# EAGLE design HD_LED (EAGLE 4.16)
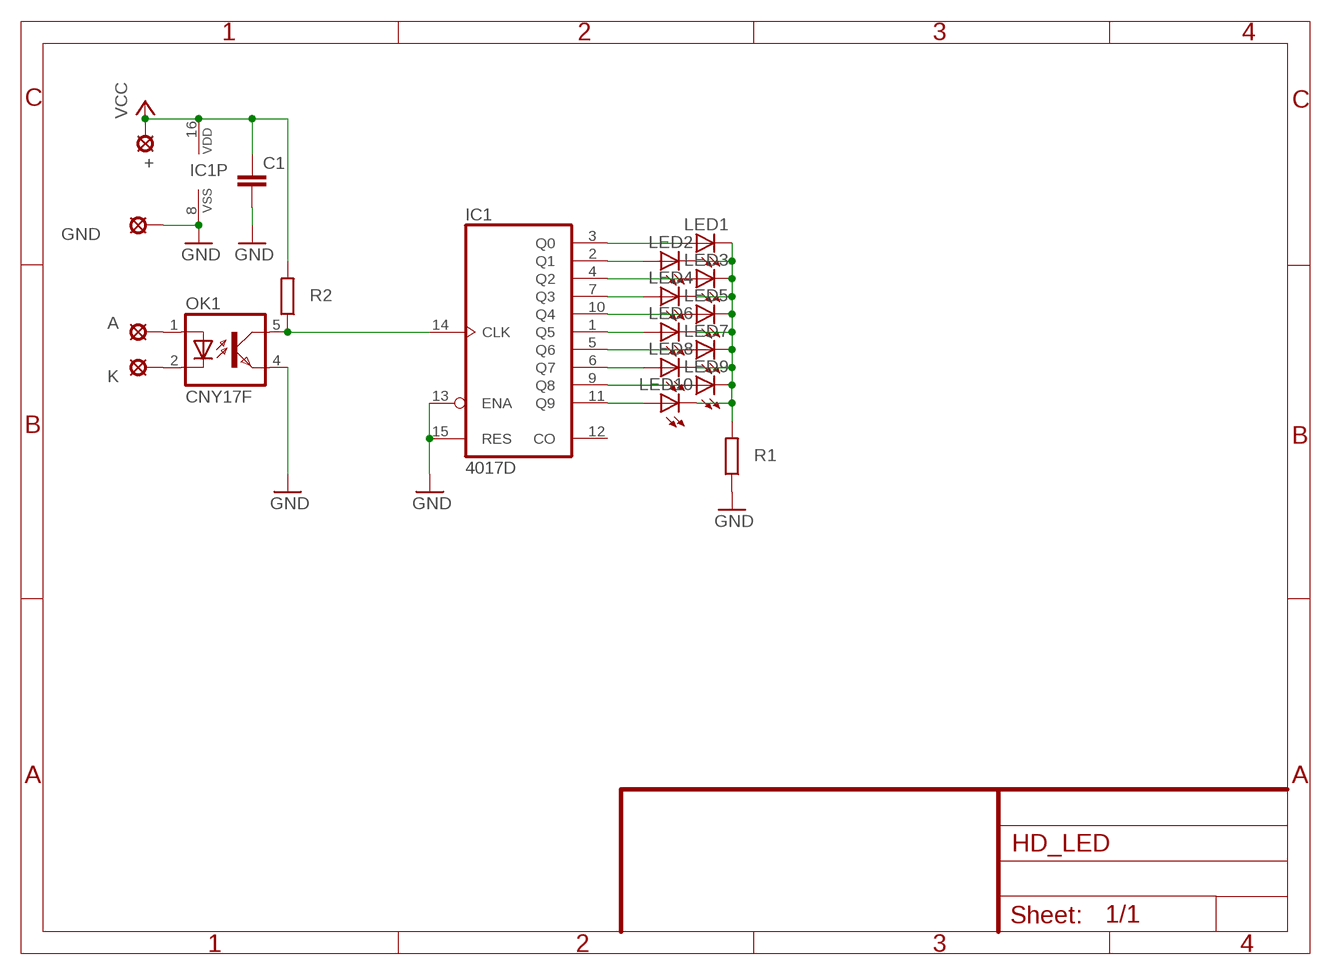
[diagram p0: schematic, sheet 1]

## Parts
+  LSP10  [LSP10]
A  LSP10  [LSP10]
C1  C-EUC0805  [C0805]
GND  LSP10  [LSP10]
IC1  4017D  [SO16]
K  LSP10  [LSP10]
LED1  LED3MM  [LED3MM]
LED2  LED3MM  [LED3MM]
LED3  LED3MM  [LED3MM]
LED4  LED3MM  [LED3MM]
LED5  LED3MM  [LED3MM]
LED6  LED3MM  [LED3MM]
LED7  LED3MM  [LED3MM]
LED8  LED3MM  [LED3MM]
LED9  LED3MM  [LED3MM]
LED10  LED3MM  [LED3MM]
OK1  CNY17F  [DIL06]
R1  R-EU_R0805  [R0805]
R2  R-EU_R0805  [R0805]

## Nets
GND: C1.2 GND.MP IC1.8(VSS) IC1.13(ENA) IC1.15(RES) OK1.4(EMIT) R1.1
N$1: IC1.3(Q0) LED1.A
N$2: IC1.2(Q1) LED2.A
N$3: IC1.4(Q2) LED3.A
N$4: IC1.7(Q3) LED4.A
N$5: IC1.10(Q4) LED5.A
N$6: IC1.1(Q5) LED6.A
N$7: IC1.5(Q6) LED7.A
N$8: IC1.6(Q7) LED8.A
N$9: IC1.9(Q8) LED9.A
N$10: IC1.11(Q9) LED10.A
N$11: LED1.K(C) LED2.K(C) LED3.K(C) LED4.K(C) LED5.K(C) LED6.K(C) LED7.K(C) LED8.K(C) LED9.K(C) LED10.K(C) R1.2
N$12: A.MP OK1.1(A)
N$13: IC1.14(CLK) OK1.5(COL) R2.1
N$14: K.MP OK1.2(C)
VCC: +.MP C1.1 IC1.16(VDD) R2.2
Unconnected: IC1.12(CO)

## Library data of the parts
+ A GND K = solpad:LSP10: SOLDER PAD
C1 = rcl:C-EU: CAPACITOR, European symbol
IC1 = 40xx:4017: COUNTER/DIVIDER
LED1-LED10 = led:LED: LED
OK1 = optocoupler:CNY17F: SIEMENS OPTO COUPLER
R1 R2 = rcl:R-EU_: RESISTOR, European symbol

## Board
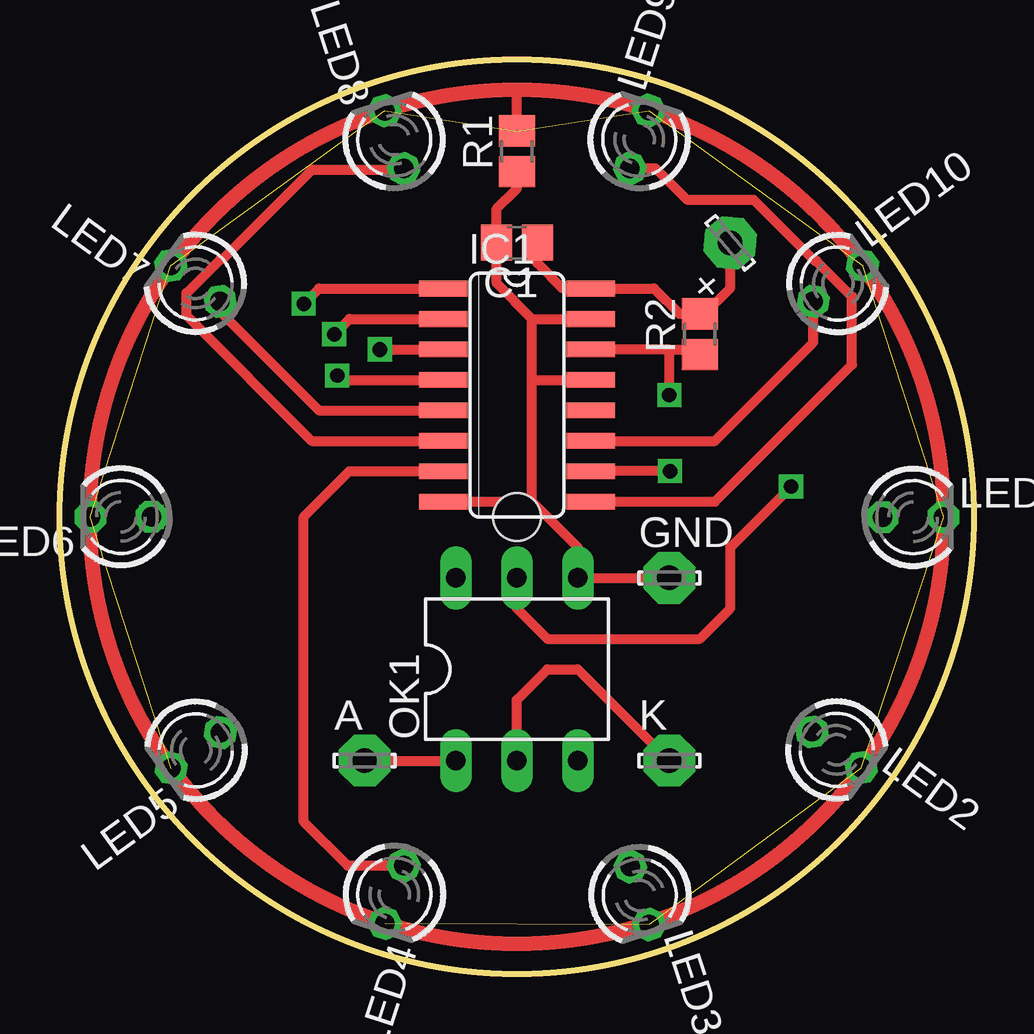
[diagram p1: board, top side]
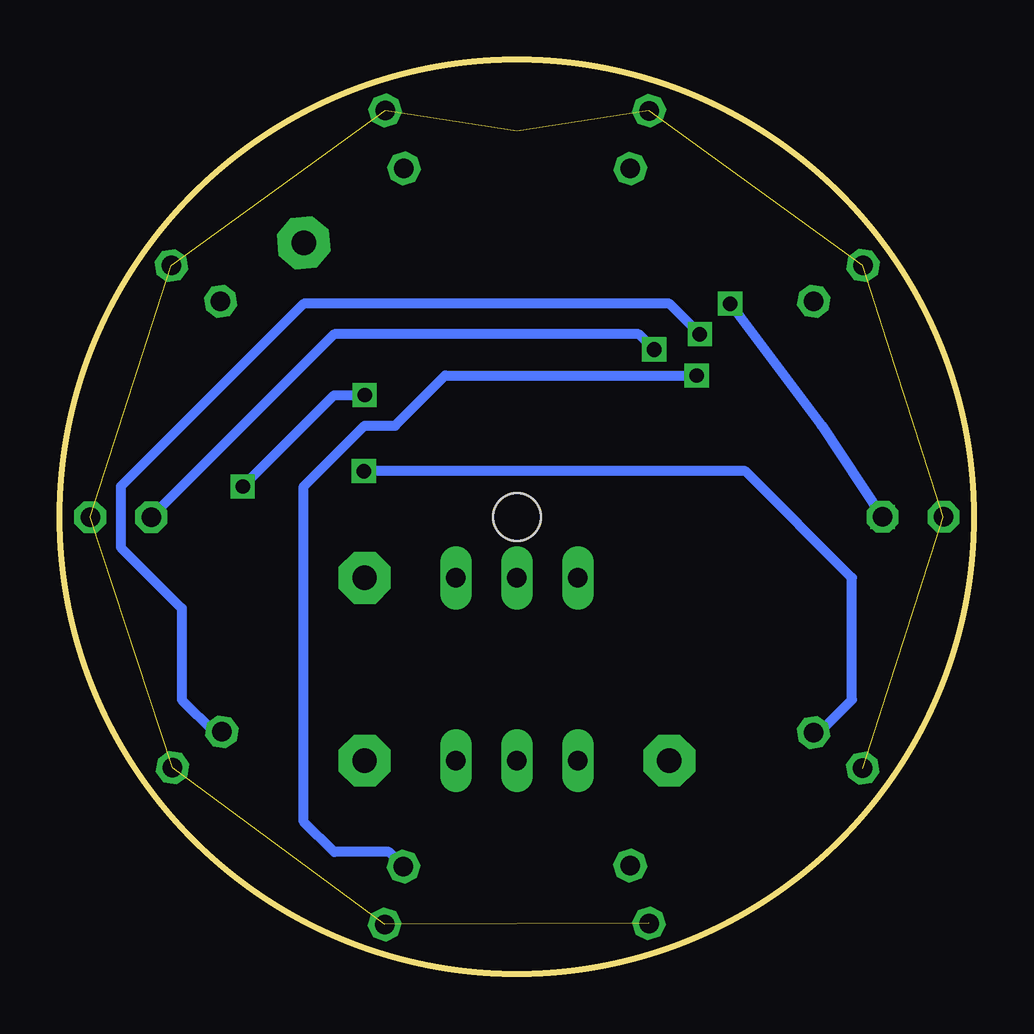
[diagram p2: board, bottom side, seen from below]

Size 38.1 x 38.1 mm. Coordinates in mm from the lower left corner, seen from the top.
Outline: circle at 19.05,19.05 radius 19.05
Copper layers (1*16): Top 0.035mm / dielectric 1.5mm / Bottom 0.035mm
Design rules "default": minimum track width 10mil, minimum drill 24mil, track to track 8mil, track to pad 8mil, pad to pad 8mil, via to via 8mil, smd to smd 8mil, copper to edge 40mil, drill to drill 8mil, minimum pad ring 10mil, minimum via ring 8mil, stop-mask expansion 4mil, vias tented up to drill 0mil, thermal gap 10mil
Holes 2 mm at 19.05,19.05

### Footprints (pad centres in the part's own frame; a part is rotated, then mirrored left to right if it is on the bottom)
LSP10 = drill 1.016 pad 2.159 octagon: MP 0,0
C0805 = smd 1.3 x 1.5: 1 -0.85,0; 2 0.85,0
SO16 = smd 0.66 x 2.032: 1 -4.445,-3.073; 2 -3.175,-3.073; 3 -1.905,-3.073; 4 -0.635,-3.073; 5 0.635,-3.073; 6 1.905,-3.073; 7 3.175,-3.073; 8 4.445,-3.073; 9 4.445,3.073; 10 3.175,3.073; 11 1.905,3.073; 12 0.635,3.073; 13 -0.635,3.073; 14 -1.905,3.073; 15 -3.175,3.073; 16 -4.445,3.073
LED3MM = drill 0.813 octagon: A -1.27,0; K 1.27,0
DIL06 = drill 0.813 long: 1 -2.54,-3.81; 2 0,-3.81; 3 2.54,-3.81; 4 2.54,3.81; 5 0,3.81; 6 -2.54,3.81
R0805 = smd 1.3 x 1.5: 1 -0.85,0; 2 0.85,0

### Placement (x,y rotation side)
+  27.94,30.48 130 top
A  12.7,8.89 0 top
C1  19.05,30.48 180 top
GND  25.4,16.51 0 top
IC1  19.05,24.13 270 top
K  25.4,8.89 0 top
LED1  35.57,19.04 0 top
LED2  32.38,9.34 324 top
LED3  24.17,3.27 288 top
LED4  13.94,3.31 252 top
LED5  5.66,9.32 216 top
LED6  2.54,19.05 180 top
LED7  5.65,28.79 144 top
LED8  13.93,34.78 108 top
LED9  24.15,34.79 72 top
LED10  32.43,28.78 36 top
OK1  19.05,12.7 0 top
R1  19.05,34.29 90 top
R2  26.67,26.67 90 top

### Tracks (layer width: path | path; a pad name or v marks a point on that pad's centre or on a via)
GND
  Top 0.406: R1.1 19.05,32.73 18.6,32.28 18.6,32.3 | 18.6,32.3 | 18.6,32.3 18.2,31.89 C1.2 18.2,28.79 19.68,27.3 | 19.68,27.3 IC1.15 | 19.68,24.77 IC1.13 | 19.68,24.77 19.68,27.3 | IC1.8 19.68,19.68 | 19.68,19.68 19.68,24.77 | 19.68,19.68 21.59,17.78 OK1.4 GND.MP
N$1  (via drill 0.6)
  Top 0.406: IC1.3 v13.34,26.04 v13.33,26.02
  Bottom 0.406: LED1.A 26.67,26.67 13.97,26.67 v13.34,26.04
N$2  (via drill 0.6)
  Top 0.406: IC1.2 12.06,27.3 v11.43,26.67
  Bottom 0.406: v11.43,26.67 12.7,27.94 27.94,27.94 35.56,20.32 35.56,17.78 33.02,15.24 33.02,11.43 31.68,10.09 LED2.A
N$3  (via drill 0.6)
  Top 0.406: IC1.4 11.74,24.77 v11.56,24.94
  Bottom 0.406: v11.56,24.94 22.05,24.94 24.13,22.86 25.4,22.86 27.94,20.32 27.94,6.35 26.67,5.08 24.38,5.08 LED3.A
N$4
  Top 0.406: IC1.7 12.06,20.95 10.16,19.05 10.16,6.35 11.99,4.52 LED4.A
N$5  (via drill 0.6)
  Top 0.406: IC1.10 v25.42,20.95 v25.43,20.96
  Bottom 0.406: v25.43,20.96 9.53,20.96 5.08,16.51 5.08,11.43 6.44,10.07 LED5.A
N$6  (via drill 0.6)
  Top 0.406: IC1.1 10.79,28.57 v10.16,27.94 | LED6.A
  Bottom 0.406: v10.16,27.94 6.35,22.86 LED6.A
  other vias: 3.81,19.05
N$7
  Top 0.406: LED7.A 6.68,27.61 10.79,23.5 IC1.5
N$8
  Top 0.406: IC1.6 10.5,22.23 5.27,27.45 5.27,28.38 6.69,29.8 6.78,29.8 10.51,33.54 14.36,33.54 | 14.36,33.54 14.37,33.54 | 14.36,33.54 LED8.A
N$9
  Top 0.406: IC1.9 27.3,19.68 33.02,25.4 33.02,28.24 31.54,29.72 31.46,29.72 28.93,32.26 26.16,32.26 24.84,33.58 LED9.A
N$10
  Top 0.406: IC1.11 27.3,22.23 31.4,26.32 LED10.A
N$11  (10 unrouted)
  Top 0.406: R1.2 19.05,36.83
N$12
  Top 0.406: A.MP OK1.1
N$13  (via drill 0.6)
  Top 0.406: R2.1 26.67,26.04 25.4,26.04 | 25.4,26.04 IC1.14 | OK1.5 19.05,15.24 20.32,13.97 26.67,13.97 27.94,15.24 27.94,17.78 v30.48,20.32 | v25.4,24.13 25.4,26.04
  Bottom 0.406: v30.48,20.32 26.67,24.13 v25.4,24.13
N$14
  Top 0.406: K.MP 21.59,12.7 20.32,12.7 19.05,11.43 OK1.2
VCC
  Top 0.406: +.MP 27.94,28.59 26.76,27.41 26.67,27.51 R2.2 25.82,27.52 24.77,28.57 IC1.16 20.95,28.57 19.9,29.63 C1.1
(copper drawn outside any net)
  shapes: Top circle x1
